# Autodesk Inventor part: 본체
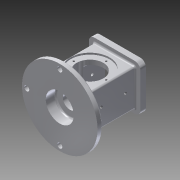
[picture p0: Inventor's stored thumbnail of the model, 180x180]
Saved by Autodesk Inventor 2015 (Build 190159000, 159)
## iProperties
Created: 2019-08
Part Number: 본체
Material: 알루미늄 6061
Document SubType Name: Modeling
Designer: a-20
Density: 2.7 g/cm^3
Appearance: 알루미늄 - 평지
Mass: 1023 g
Surface Area: 817.999 cm^2
Volume: 378.89 cm^3
Author: a-20
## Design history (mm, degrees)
sketch "스케치1"
  geometry: L1 (37, 33)-(-37, 33); L2 (-37, 33)-(-37, -33); L3 (-37, -33)-(37, -33); L4 (37, -33)-(37, 33); L5 (37, 33)-(-37, -33); 2 further points
  constraints: 10 end point, 2 parallel, 1 coincident, 1 horizontal, 1 midpoint, 1 perpendicular
  dimensions: "d0" = 66 distance of L3.end L1.start; "d1" = 74 distance of L1.start L1.end
extrude "돌출1" new body sketch "스케치1" stored distance "d2" = 108; taper "d3" = 0 deg
sketch "스케치2"
  geometry: L1 (0, 57.453)-(0, -57.453); L2 (0, 33)-(35, 33); L3 (35, 33)-(35, 30); L4 (35, 30)-(24, 30); L5 (24, 30)-(24, -30); L6 (24, -30)-(35, -30); L7 (35, -30)-(35, -33); L8 (35, -33)-(0, -33); 2 further points
  constraints: 16 end point, 5 perpendicular, 4 point on line, 1 coincident, 1 horizontal, 1 midpoint, 1 vertical
  dimensions: "d4" = 70 diameter of L3 L1; "d5" = 48 diameter of L5 L1; "d7" = 33 distance from line of point (0, 0) L2; "d8" = 3 distance between parallel lines of L2 L4; "d9" = 3 distance between parallel lines of L8 L6; "d84" = 66 distance between parallel lines of L8 L2
revolve "회전1" sketch "스케치2" stored, may be unused: angle "d10" = 90 deg
sketch "스케치3"
  geometry: C1 r 67.5 at (0, 0); 1 further point
  constraints: 1 centre point, 1 coincident
  dimensions: "d11" = 135 diameter of C1
extrude "돌출2" join sketch "스케치3" distance "d12" = 10; taper "d13" = 0 deg
sketch "스케치4"
  geometry: L1 (-46, -41)-(46, -41); L2 (46, -41)-(46, 41); L3 (46, 41)-(-46, 41); L4 (-46, 41)-(-46, -41); L5 (-46, -41)-(46, 41); 2 further points
  constraints: 10 end point, 2 parallel, 1 coincident, 1 horizontal, 1 midpoint, 1 perpendicular
  dimensions: "d14" = 82 distance of L3.end L1.start; "d15" = 92 distance of L1.start L1.end
extrude "돌출3" join sketch "스케치4" distance "d16" = 10; taper "d17" = 0 deg
sketch "스케치5"
  geometry: L1 (-26, -26)-(26, -26); L2 (26, -26)-(26, 26); L3 (26, 26)-(-26, 26); L4 (-26, 26)-(-26, -26); L5 (-26, -26)-(26, 26); 2 further points
  constraints: 10 end point, 2 parallel, 1 coincident, 1 horizontal, 1 midpoint, 1 perpendicular
  dimensions: "d18" = 52 distance of L3.end L1.start; "d19" = 52 distance of L2.end L3.end
extrude "돌출4" cut sketch "스케치5" distance "d20" = 8; taper "d21" = 0 deg
sketch "스케치6"
  geometry: L1 (-22, -22)-(22, -22); L2 (22, -22)-(22, 22); L3 (22, 22)-(-22, 22); L4 (-22, 22)-(-22, -22); L5 (-22, -22)-(22, 22); 2 further points
  constraints: 10 end point, 2 parallel, 1 coincident, 1 horizontal, 1 midpoint, 1 perpendicular
  dimensions: "d22" = 44 distance of L3.end L1.start; "d23" = 44 distance of L1.start L1.end
extrude "돌출5" cut sketch "스케치6" distance "d24" = 74; taper "d25" = 0 deg
sketch "스케치7"
  geometry: L1 (-64.131, 0)-(0, 0); L2 (-54, -67.5)-(-54, 67.5) reference; L3 (-54, 0)-(-54, 25); L4 (-36, 25)-(-36, 12.5); L5 (-36, 12.5)-(-20.187, 12.5); L6 (-20.187, 12.5)-(-20.187, 0); L7 (-54, 25)-(-36, 25); L8 (-20.187, 0)-(-54, 0)
  constraints: 14 end point, 2 horizontal, 2 perpendicular, 2 point on line, 1 collinear, 1 midpoint, 1 vertical
  dimensions: "d26" = 50 diameter of L7 L1; "d27" = 25 diameter of L5 L1; "d28" = 18 distance between parallel lines of L4 L2; "d29" = 33.81323 distance between parallel lines of L6 L2
revolve "회전2" sketch "스케치7" stored, may be unused: angle "d30" = 90 deg
sketch "스케치10"
  geometry: L1 (0, 0)-(0, 59)
  constraints: 2 end point, 1 vertical
  dimensions: "d51" = 59 distance of L1.start L1.end
hole "구멍3" sketch "스케치10" at (0, 59) diameter "d52" = 9; stored, may be unused: countersink angle "d56" = 90 deg, drill point angle "d58" = 118 deg; dims "d53" = 12, "d54" = 4, "d55" = 2, "d57" = 17.1
sketch "스케치11"
  geometry: L1 (-36, 31)-(36, 31); L2 (36, 31)-(36, -31); L3 (36, -31)-(-36, -31); L4 (-36, -31)-(-36, 31); L5 (-36, 31)-(36, -31); 6 further points
  constraints: 10 end point, 5 coincident, 2 parallel, 1 horizontal, 1 midpoint, 1 perpendicular
  dimensions: "d62" = 72 distance of L1.start L1.end; "d63" = 62 distance of L1.end L2.end
hole "구멍4" sketch "스케치11" at (-36, 31), (36, 31), (36, -31), (-36, -31) diameter "d64" = 3.242; stored, may be unused: countersink angle "d68" = 90 deg, drill point angle "d70" = 118 deg; dims "d65" = 4, "d66" = 4, "d67" = 2, "d69" = 6
fillet "모깎기1" dims "d71" = 10
fillet "모깎기3" dims "d73" = 3
chamfer "모따기1" distance "d74" = 3; stored, may be unused: second distance "d75" = 2, angle "d76" = 45 deg
chamfer "모따기2" distance "d77" = 1; stored, may be unused: second distance "d78" = 2, angle "d79" = 45 deg
sketch "스케치12"
  geometry: C1 r 59 at (0, 0); 1 further point
  constraints: 1 centre point, 1 coincident, 1 other
  dimensions: "d80" = 118 diameter of C1
feature "엠보싱1" sketch "스케치12" dims "d0" = 66, "d1" = 74, "d11" = 135, "d81" = 0.5, "d82" = 0
fillet "모깎기4" dims "d83" = 3
sketch "스케치13"
  geometry: L1 (34, -41)-(34, -12)
  constraints: 2 end point, 1 vertical
  dimensions: "d85" = 29 distance of L1.start L1.end
hole "구멍5" sketch "스케치13" at (34, -12) diameter "d86" = 3.242; stored, may be unused: countersink angle "d90" = 90 deg, drill point angle "d92" = 118 deg; dims "d87" = 4, "d88" = 4, "d89" = 2, "d91" = 6
sketch "스케치14"
  geometry: L1 (55, -10)-(5, -10) reference; L2 (30, 44)-(30, 70); L3 (30, 44)-(30, 27)
  constraints: 4 end point, 2 vertical
  dimensions: "d96" = 37 distance from line of L1 L3.end; "d97" = 43 distance of L2.end L3.end
hole "구멍6" sketch "스케치14" at (30, 70), (30, 27) diameter "d98" = 4.917; stored, may be unused: countersink angle "d102" = 90 deg, drill point angle "d104" = 118 deg; dims "d99" = 12, "d100" = 4, "d101" = 2, "d103" = 17.1
node "솔리드1"
pattern_circular "원형 패턴2" dims angle "d60" = -180 deg
pattern_circular "원형 패턴3" dims angle "d94" = 360 deg
mirror "대칭3"
mirror "대칭4"
